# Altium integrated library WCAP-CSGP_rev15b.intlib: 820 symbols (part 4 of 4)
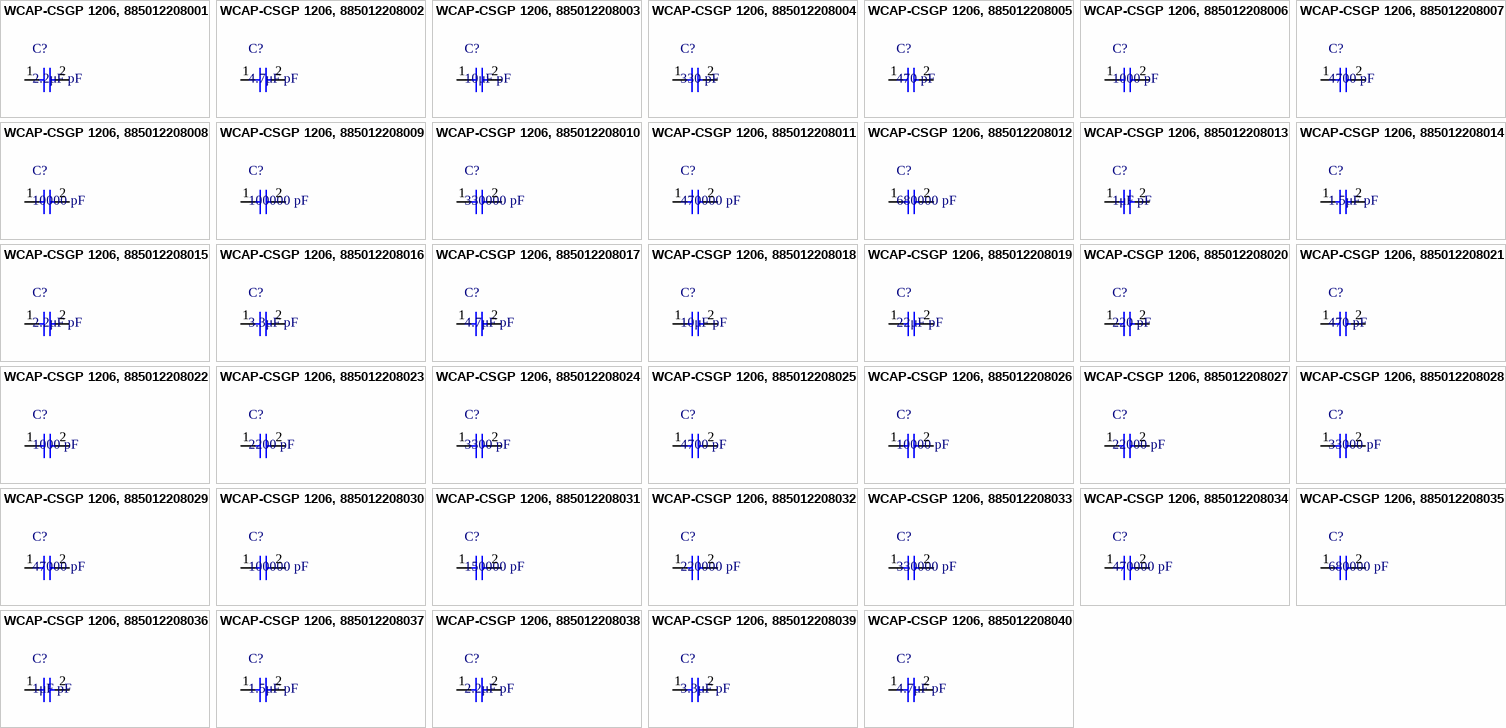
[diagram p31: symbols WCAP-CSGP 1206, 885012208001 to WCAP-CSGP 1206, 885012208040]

## WCAP-CSGP 1206, 885012208033
designator C?, comment 330000 pF
WCAP-CSGP MLCC, X7R, 1206, 330000 pF,16Vdc; Manufacturer: Wurth Elektronik; partNo: 885012208033; E-mail: libraries@we-online.com
footprint WCAP-CSGP 1206, H=0.95mm
pins: 1, 2

## WCAP-CSGP 1206, 885012208034
designator C?, comment 470000 pF
WCAP-CSGP MLCC, X7R, 1206, 470000 pF,16Vdc; Manufacturer: Wurth Elektronik; partNo: 885012208034; E-mail: libraries@we-online.com
footprint WCAP-CSGP 1206, H=1.15mm
pins: 1, 2

## WCAP-CSGP 1206, 885012208035
designator C?, comment 680000 pF
WCAP-CSGP MLCC, X7R, 1206, 680000 pF,16Vdc; Manufacturer: Wurth Elektronik; partNo: 885012208035; E-mail: libraries@we-online.com
footprint WCAP-CSGP 1206, H=1.15mm
pins: 1, 2

## WCAP-CSGP 1206, 885012208036
designator C?, comment 1μF pF
WCAP-CSGP MLCC, X7R, 1206, 1μF pF,16Vdc; Manufacturer: Wurth Elektronik; partNo: 885012208036; E-mail: libraries@we-online.com
footprint WCAP-CSGP 1206, H=1.15mm
pins: 1, 2

## WCAP-CSGP 1206, 885012208037
designator C?, comment 1.5μF pF
WCAP-CSGP MLCC, X7R, 1206, 1.5μF pF,16Vdc; Manufacturer: Wurth Elektronik; partNo: 885012208037; E-mail: libraries@we-online.com
footprint WCAP-CSGP 1206, H=1.15mm
pins: 1, 2

## WCAP-CSGP 1206, 885012208038
designator C?, comment 2.2μF pF
WCAP-CSGP MLCC, X7R, 1206, 2.2μF pF,16Vdc; Manufacturer: Wurth Elektronik; partNo: 885012208038; E-mail: libraries@we-online.com
footprint WCAP-CSGP 1206, H=1.15mm
pins: 1, 2

## WCAP-CSGP 1206, 885012208039
designator C?, comment 3.3μF pF
WCAP-CSGP MLCC, X7R, 1206, 3.3μF pF,16Vdc; Manufacturer: Wurth Elektronik; partNo: 885012208039; E-mail: libraries@we-online.com
footprint WCAP-CSGP 1206, H=1.6mm
pins: 1, 2

## WCAP-CSGP 1206, 885012208040
designator C?, comment 4.7μF pF
WCAP-CSGP MLCC, X7R, 1206, 4.7μF pF,16Vdc; Manufacturer: Wurth Elektronik; partNo: 885012208040; E-mail: libraries@we-online.com
footprint WCAP-CSGP 1206, H=1.6mm
pins: 1, 2

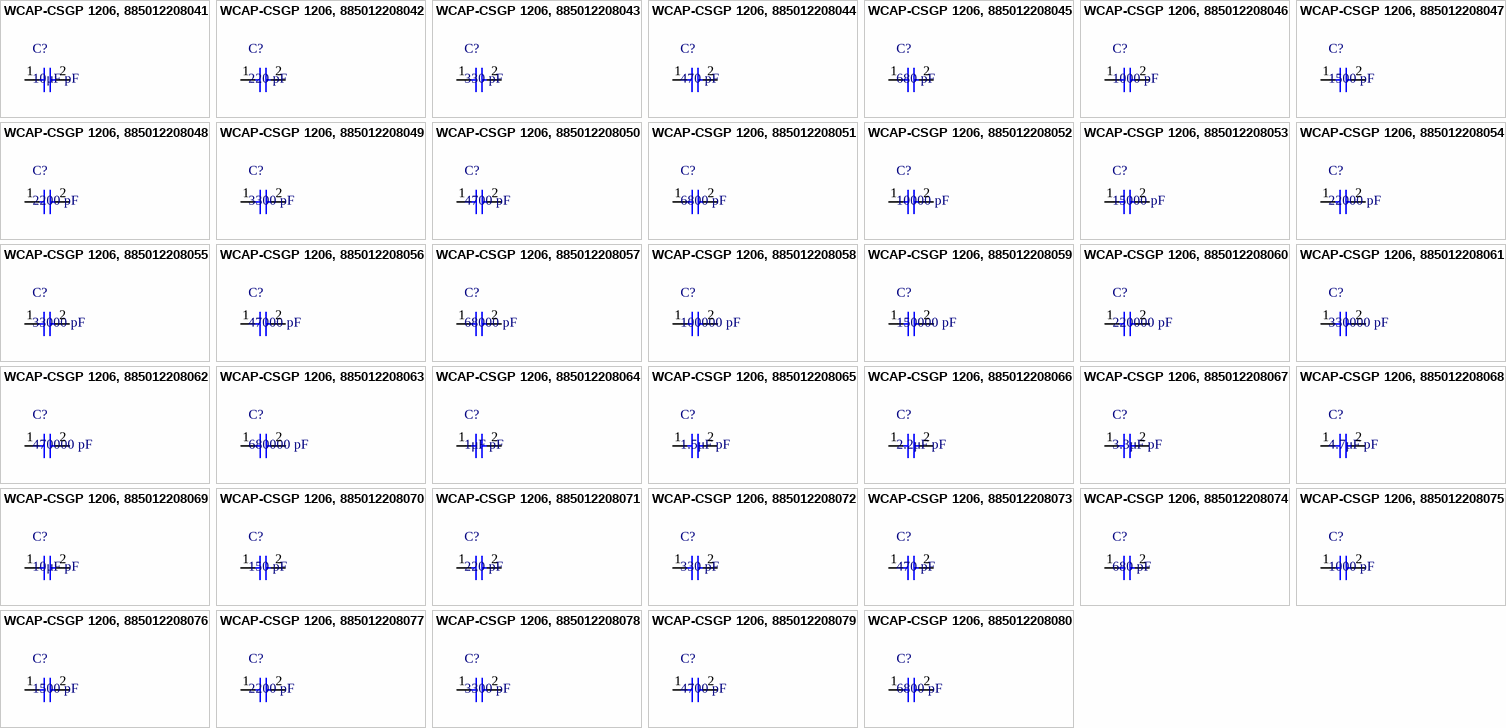
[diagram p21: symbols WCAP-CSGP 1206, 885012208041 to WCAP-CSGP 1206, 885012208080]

## WCAP-CSGP 1206, 885012208041
designator C?, comment 10μF pF
WCAP-CSGP MLCC, X7R, 1206, 10μF pF,16Vdc; Manufacturer: Wurth Elektronik; partNo: 885012208041; E-mail: libraries@we-online.com
footprint WCAP-CSGP 1206, H=1.6mm
pins: 1, 2

## WCAP-CSGP 1206, 885012208042
designator C?, comment 220 pF
WCAP-CSGP MLCC, X7R, 1206, 220 pF,25Vdc; Manufacturer: Wurth Elektronik; partNo: 885012208042; E-mail: libraries@we-online.com
footprint WCAP-CSGP 1206, H=0.8mm
pins: 1, 2

## WCAP-CSGP 1206, 885012208043
designator C?, comment 330 pF
WCAP-CSGP MLCC, X7R, 1206, 330 pF,25Vdc; Manufacturer: Wurth Elektronik; partNo: 885012208043; E-mail: libraries@we-online.com
footprint WCAP-CSGP 1206, H=0.8mm
pins: 1, 2

## WCAP-CSGP 1206, 885012208044
designator C?, comment 470 pF
WCAP-CSGP MLCC, X7R, 1206, 470 pF,25Vdc; Manufacturer: Wurth Elektronik; partNo: 885012208044; E-mail: libraries@we-online.com
footprint WCAP-CSGP 1206, H=0.8mm
pins: 1, 2

## WCAP-CSGP 1206, 885012208045
designator C?, comment 680 pF
WCAP-CSGP MLCC, X7R, 1206, 680 pF,25Vdc; Manufacturer: Wurth Elektronik; partNo: 885012208045; E-mail: libraries@we-online.com
footprint WCAP-CSGP 1206, H=0.8mm
pins: 1, 2

## WCAP-CSGP 1206, 885012208046
designator C?, comment 1000 pF
WCAP-CSGP MLCC, X7R, 1206, 1000 pF,25Vdc; Manufacturer: Wurth Elektronik; partNo: 885012208046; E-mail: libraries@we-online.com
footprint WCAP-CSGP 1206, H=0.8mm
pins: 1, 2

## WCAP-CSGP 1206, 885012208047
designator C?, comment 1500 pF
WCAP-CSGP MLCC, X7R, 1206, 1500 pF,25Vdc; Manufacturer: Wurth Elektronik; partNo: 885012208047; E-mail: libraries@we-online.com
footprint WCAP-CSGP 1206, H=0.8mm
pins: 1, 2

## WCAP-CSGP 1206, 885012208048
designator C?, comment 2200 pF
WCAP-CSGP MLCC, X7R, 1206, 2200 pF,25Vdc; Manufacturer: Wurth Elektronik; partNo: 885012208048; E-mail: libraries@we-online.com
footprint WCAP-CSGP 1206, H=0.8mm
pins: 1, 2

## WCAP-CSGP 1206, 885012208049
designator C?, comment 3300 pF
WCAP-CSGP MLCC, X7R, 1206, 3300 pF,25Vdc; Manufacturer: Wurth Elektronik; partNo: 885012208049; E-mail: libraries@we-online.com
footprint WCAP-CSGP 1206, H=0.8mm
pins: 1, 2

## WCAP-CSGP 1206, 885012208050
designator C?, comment 4700 pF
WCAP-CSGP MLCC, X7R, 1206, 4700 pF,25Vdc; Manufacturer: Wurth Elektronik; partNo: 885012208050; E-mail: libraries@we-online.com
footprint WCAP-CSGP 1206, H=0.8mm
pins: 1, 2

## WCAP-CSGP 1206, 885012208051
designator C?, comment 6800 pF
WCAP-CSGP MLCC, X7R, 1206, 6800 pF,25Vdc; Manufacturer: Wurth Elektronik; partNo: 885012208051; E-mail: libraries@we-online.com
footprint WCAP-CSGP 1206, H=0.8mm
pins: 1, 2

## WCAP-CSGP 1206, 885012208052
designator C?, comment 10000 pF
WCAP-CSGP MLCC, X7R, 1206, 10000 pF,25Vdc; Manufacturer: Wurth Elektronik; partNo: 885012208052; E-mail: libraries@we-online.com
footprint WCAP-CSGP 1206, H=0.8mm
pins: 1, 2

## WCAP-CSGP 1206, 885012208053
designator C?, comment 15000 pF
WCAP-CSGP MLCC, X7R, 1206, 15000 pF,25Vdc; Manufacturer: Wurth Elektronik; partNo: 885012208053; E-mail: libraries@we-online.com
footprint WCAP-CSGP 1206, H=0.8mm
pins: 1, 2

## WCAP-CSGP 1206, 885012208054
designator C?, comment 22000 pF
WCAP-CSGP MLCC, X7R, 1206, 22000 pF,25Vdc; Manufacturer: Wurth Elektronik; partNo: 885012208054; E-mail: libraries@we-online.com
footprint WCAP-CSGP 1206, H=0.8mm
pins: 1, 2

## WCAP-CSGP 1206, 885012208055
designator C?, comment 33000 pF
WCAP-CSGP MLCC, X7R, 1206, 33000 pF,25Vdc; Manufacturer: Wurth Elektronik; partNo: 885012208055; E-mail: libraries@we-online.com
footprint WCAP-CSGP 1206, H=0.8mm
pins: 1, 2

## WCAP-CSGP 1206, 885012208056
designator C?, comment 47000 pF
WCAP-CSGP MLCC, X7R, 1206, 47000 pF,25Vdc; Manufacturer: Wurth Elektronik; partNo: 885012208056; E-mail: libraries@we-online.com
footprint WCAP-CSGP 1206, H=0.8mm
pins: 1, 2

## WCAP-CSGP 1206, 885012208057
designator C?, comment 68000 pF
WCAP-CSGP MLCC, X7R, 1206, 68000 pF,25Vdc; Manufacturer: Wurth Elektronik; partNo: 885012208057; E-mail: libraries@we-online.com
footprint WCAP-CSGP 1206, H=0.8mm
pins: 1, 2

## WCAP-CSGP 1206, 885012208058
designator C?, comment 100000 pF
WCAP-CSGP MLCC, X7R, 1206, 100000 pF,25Vdc; Manufacturer: Wurth Elektronik; partNo: 885012208058; E-mail: libraries@we-online.com
footprint WCAP-CSGP 1206, H=0.8mm
pins: 1, 2

## WCAP-CSGP 1206, 885012208059
designator C?, comment 150000 pF
WCAP-CSGP MLCC, X7R, 1206, 150000 pF,25Vdc; Manufacturer: Wurth Elektronik; partNo: 885012208059; E-mail: libraries@we-online.com
footprint WCAP-CSGP 1206, H=0.95mm
pins: 1, 2

## WCAP-CSGP 1206, 885012208060
designator C?, comment 220000 pF
WCAP-CSGP MLCC, X7R, 1206, 220000 pF,25Vdc; Manufacturer: Wurth Elektronik; partNo: 885012208060; E-mail: libraries@we-online.com
footprint WCAP-CSGP 1206, H=0.95mm
pins: 1, 2

## WCAP-CSGP 1206, 885012208061
designator C?, comment 330000 pF
WCAP-CSGP MLCC, X7R, 1206, 330000 pF,25Vdc; Manufacturer: Wurth Elektronik; partNo: 885012208061; E-mail: libraries@we-online.com
footprint WCAP-CSGP 1206, H=0.95mm
pins: 1, 2

## WCAP-CSGP 1206, 885012208062
designator C?, comment 470000 pF
WCAP-CSGP MLCC, X7R, 1206, 470000 pF,25Vdc; Manufacturer: Wurth Elektronik; partNo: 885012208062; E-mail: libraries@we-online.com
footprint WCAP-CSGP 1206, H=1.15mm
pins: 1, 2

## WCAP-CSGP 1206, 885012208063
designator C?, comment 680000 pF
WCAP-CSGP MLCC, X7R, 1206, 680000 pF,25Vdc; Manufacturer: Wurth Elektronik; partNo: 885012208063; E-mail: libraries@we-online.com
footprint WCAP-CSGP 1206, H=1.15mm
pins: 1, 2

## WCAP-CSGP 1206, 885012208064
designator C?, comment 1μF pF
WCAP-CSGP MLCC, X7R, 1206, 1μF pF,25Vdc; Manufacturer: Wurth Elektronik; partNo: 885012208064; E-mail: libraries@we-online.com
footprint WCAP-CSGP 1206, H=1.15mm
pins: 1, 2

## WCAP-CSGP 1206, 885012208065
designator C?, comment 1.5μF pF
WCAP-CSGP MLCC, X7R, 1206, 1.5μF pF,25Vdc; Manufacturer: Wurth Elektronik; partNo: 885012208065; E-mail: libraries@we-online.com
footprint WCAP-CSGP 1206, H=1.6mm
pins: 1, 2

## WCAP-CSGP 1206, 885012208066
designator C?, comment 2.2μF pF
WCAP-CSGP MLCC, X7R, 1206, 2.2μF pF,25Vdc; Manufacturer: Wurth Elektronik; partNo: 885012208066; E-mail: libraries@we-online.com
footprint WCAP-CSGP 1206, H=1.6mm
pins: 1, 2

## WCAP-CSGP 1206, 885012208067
designator C?, comment 3.3μF pF
WCAP-CSGP MLCC, X7R, 1206, 3.3μF pF,25Vdc; Manufacturer: Wurth Elektronik; partNo: 885012208067; E-mail: libraries@we-online.com
footprint WCAP-CSGP 1206, H=1.6mm
pins: 1, 2

## WCAP-CSGP 1206, 885012208068
designator C?, comment 4.7μF pF
WCAP-CSGP MLCC, X7R, 1206, 4.7μF pF,25Vdc; Manufacturer: Wurth Elektronik; partNo: 885012208068; E-mail: libraries@we-online.com
footprint WCAP-CSGP 1206, H=1.6mm
pins: 1, 2

## WCAP-CSGP 1206, 885012208069
designator C?, comment 10μF pF
WCAP-CSGP MLCC, X7R, 1206, 10μF pF,25Vdc; Manufacturer: Wurth Elektronik; partNo: 885012208069; E-mail: libraries@we-online.com
footprint WCAP-CSGP 1206, H=1.6mm
pins: 1, 2

## WCAP-CSGP 1206, 885012208070
designator C?, comment 150 pF
WCAP-CSGP MLCC, X7R, 1206, 150 pF,50Vdc; Manufacturer: Wurth Elektronik; partNo: 885012208070; E-mail: libraries@we-online.com
footprint WCAP-CSGP 1206, H=0.8mm
pins: 1, 2

## WCAP-CSGP 1206, 885012208071
designator C?, comment 220 pF
WCAP-CSGP MLCC, X7R, 1206, 220 pF,50Vdc; Manufacturer: Wurth Elektronik; partNo: 885012208071; E-mail: libraries@we-online.com
footprint WCAP-CSGP 1206, H=0.8mm
pins: 1, 2

## WCAP-CSGP 1206, 885012208072
designator C?, comment 330 pF
WCAP-CSGP MLCC, X7R, 1206, 330 pF,50Vdc; Manufacturer: Wurth Elektronik; partNo: 885012208072; E-mail: libraries@we-online.com
footprint WCAP-CSGP 1206, H=0.8mm
pins: 1, 2

## WCAP-CSGP 1206, 885012208073
designator C?, comment 470 pF
WCAP-CSGP MLCC, X7R, 1206, 470 pF,50Vdc; Manufacturer: Wurth Elektronik; partNo: 885012208073; E-mail: libraries@we-online.com
footprint WCAP-CSGP 1206, H=0.8mm
pins: 1, 2

## WCAP-CSGP 1206, 885012208074
designator C?, comment 680 pF
WCAP-CSGP MLCC, X7R, 1206, 680 pF,50Vdc; Manufacturer: Wurth Elektronik; partNo: 885012208074; E-mail: libraries@we-online.com
footprint WCAP-CSGP 1206, H=0.8mm
pins: 1, 2

## WCAP-CSGP 1206, 885012208075
designator C?, comment 1000 pF
WCAP-CSGP MLCC, X7R, 1206, 1000 pF,50Vdc; Manufacturer: Wurth Elektronik; partNo: 885012208075; E-mail: libraries@we-online.com
footprint WCAP-CSGP 1206, H=0.8mm
pins: 1, 2

## WCAP-CSGP 1206, 885012208076
designator C?, comment 1500 pF
WCAP-CSGP MLCC, X7R, 1206, 1500 pF,50Vdc; Manufacturer: Wurth Elektronik; partNo: 885012208076; E-mail: libraries@we-online.com
footprint WCAP-CSGP 1206, H=0.8mm
pins: 1, 2

## WCAP-CSGP 1206, 885012208077
designator C?, comment 2200 pF
WCAP-CSGP MLCC, X7R, 1206, 2200 pF,50Vdc; Manufacturer: Wurth Elektronik; partNo: 885012208077; E-mail: libraries@we-online.com
footprint WCAP-CSGP 1206, H=0.8mm
pins: 1, 2

## WCAP-CSGP 1206, 885012208078
designator C?, comment 3300 pF
WCAP-CSGP MLCC, X7R, 1206, 3300 pF,50Vdc; Manufacturer: Wurth Elektronik; partNo: 885012208078; E-mail: libraries@we-online.com
footprint WCAP-CSGP 1206, H=0.8mm
pins: 1, 2

## WCAP-CSGP 1206, 885012208079
designator C?, comment 4700 pF
WCAP-CSGP MLCC, X7R, 1206, 4700 pF,50Vdc; Manufacturer: Wurth Elektronik; partNo: 885012208079; E-mail: libraries@we-online.com
footprint WCAP-CSGP 1206, H=0.8mm
pins: 1, 2

## WCAP-CSGP 1206, 885012208080
designator C?, comment 6800 pF
WCAP-CSGP MLCC, X7R, 1206, 6800 pF,50Vdc; Manufacturer: Wurth Elektronik; partNo: 885012208080; E-mail: libraries@we-online.com
footprint WCAP-CSGP 1206, H=0.8mm
pins: 1, 2

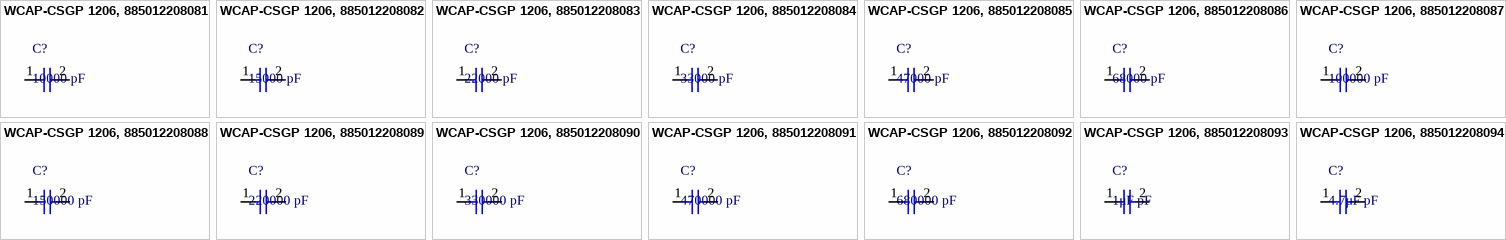
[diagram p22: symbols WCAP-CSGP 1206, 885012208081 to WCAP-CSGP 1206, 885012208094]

## WCAP-CSGP 1206, 885012208081
designator C?, comment 10000 pF
WCAP-CSGP MLCC, X7R, 1206, 10000 pF,50Vdc; Manufacturer: Wurth Elektronik; partNo: 885012208081; E-mail: libraries@we-online.com
footprint WCAP-CSGP 1206, H=0.8mm
pins: 1, 2

## WCAP-CSGP 1206, 885012208082
designator C?, comment 15000 pF
WCAP-CSGP MLCC, X7R, 1206, 15000 pF,50Vdc; Manufacturer: Wurth Elektronik; partNo: 885012208082; E-mail: libraries@we-online.com
footprint WCAP-CSGP 1206, H=0.8mm
pins: 1, 2

## WCAP-CSGP 1206, 885012208083
designator C?, comment 22000 pF
WCAP-CSGP MLCC, X7R, 1206, 22000 pF,50Vdc; Manufacturer: Wurth Elektronik; partNo: 885012208083; E-mail: libraries@we-online.com
footprint WCAP-CSGP 1206, H=0.8mm
pins: 1, 2

## WCAP-CSGP 1206, 885012208084
designator C?, comment 33000 pF
WCAP-CSGP MLCC, X7R, 1206, 33000 pF,50Vdc; Manufacturer: Wurth Elektronik; partNo: 885012208084; E-mail: libraries@we-online.com
footprint WCAP-CSGP 1206, H=0.8mm
pins: 1, 2

## WCAP-CSGP 1206, 885012208085
designator C?, comment 47000 pF
WCAP-CSGP MLCC, X7R, 1206, 47000 pF,50Vdc; Manufacturer: Wurth Elektronik; partNo: 885012208085; E-mail: libraries@we-online.com
footprint WCAP-CSGP 1206, H=0.8mm
pins: 1, 2

## WCAP-CSGP 1206, 885012208086
designator C?, comment 68000 pF
WCAP-CSGP MLCC, X7R, 1206, 68000 pF,50Vdc; Manufacturer: Wurth Elektronik; partNo: 885012208086; E-mail: libraries@we-online.com
footprint WCAP-CSGP 1206, H=0.8mm
pins: 1, 2

## WCAP-CSGP 1206, 885012208087
designator C?, comment 100000 pF
WCAP-CSGP MLCC, X7R, 1206, 100000 pF,50Vdc; Manufacturer: Wurth Elektronik; partNo: 885012208087; E-mail: libraries@we-online.com
footprint WCAP-CSGP 1206, H=0.8mm
pins: 1, 2

## WCAP-CSGP 1206, 885012208088
designator C?, comment 150000 pF
WCAP-CSGP MLCC, X7R, 1206, 150000 pF,50Vdc; Manufacturer: Wurth Elektronik; partNo: 885012208088; E-mail: libraries@we-online.com
footprint WCAP-CSGP 1206, H=0.95mm
pins: 1, 2

## WCAP-CSGP 1206, 885012208089
designator C?, comment 220000 pF
WCAP-CSGP MLCC, X7R, 1206, 220000 pF,50Vdc; Manufacturer: Wurth Elektronik; partNo: 885012208089; E-mail: libraries@we-online.com
footprint WCAP-CSGP 1206, H=0.95mm
pins: 1, 2

## WCAP-CSGP 1206, 885012208090
designator C?, comment 330000 pF
WCAP-CSGP MLCC, X7R, 1206, 330000 pF,50Vdc; Manufacturer: Wurth Elektronik; partNo: 885012208090; E-mail: libraries@we-online.com
footprint WCAP-CSGP 1206, H=1.25mm
pins: 1, 2

## WCAP-CSGP 1206, 885012208091
designator C?, comment 470000 pF
WCAP-CSGP MLCC, X7R, 1206, 470000 pF,50Vdc; Manufacturer: Wurth Elektronik; partNo: 885012208091; E-mail: libraries@we-online.com
footprint WCAP-CSGP 1206, H=1.6mm
pins: 1, 2

## WCAP-CSGP 1206, 885012208092
designator C?, comment 680000 pF
WCAP-CSGP MLCC, X7R, 1206, 680000 pF,50Vdc; Manufacturer: Wurth Elektronik; partNo: 885012208092; E-mail: libraries@we-online.com
footprint WCAP-CSGP 1206, H=1.6mm
pins: 1, 2

## WCAP-CSGP 1206, 885012208093
designator C?, comment 1μF pF
WCAP-CSGP MLCC, X7R, 1206, 1μF pF,50Vdc; Manufacturer: Wurth Elektronik; partNo: 885012208093; E-mail: libraries@we-online.com
footprint WCAP-CSGP 1206, H=1.6mm
pins: 1, 2

## WCAP-CSGP 1206, 885012208094
designator C?, comment 4.7μF pF
WCAP-CSGP MLCC, X7R, 1206, 4.7μF pF,50Vdc; Manufacturer: Wurth Elektronik; partNo: 885012208094; E-mail: libraries@we-online.com
footprint WCAP-CSGP 1206, H=1.6mm
pins: 1, 2


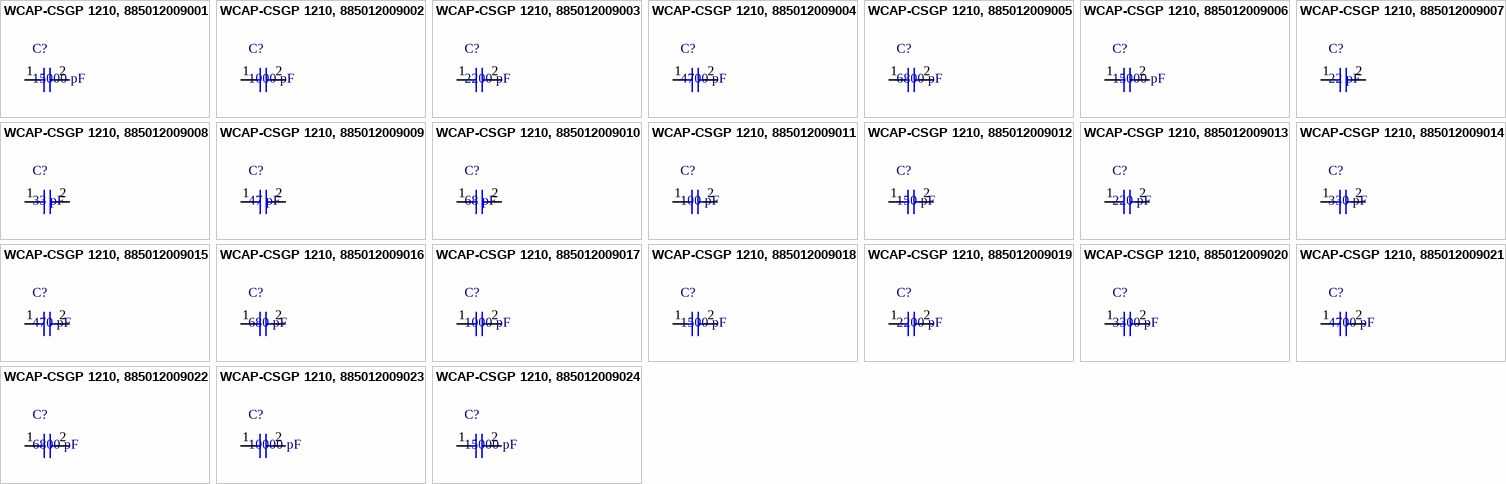
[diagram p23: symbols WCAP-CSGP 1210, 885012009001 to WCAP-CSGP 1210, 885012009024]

## WCAP-CSGP 1210, 885012009001
designator C?, comment 15000 pF
WCAP-CSGP MLCC, NP0, 1210, 15000 pF,16Vdc; Manufacturer: Wurth Elektronik; partNo: 885012009001; E-mail: libraries@we-online.com
footprint WCAP-CSGP 1210, H=1.25mm (MLCC 1210, H=0.95mm)
pins: 1, 2

## WCAP-CSGP 1210, 885012009002
designator C?, comment 1000 pF
WCAP-CSGP MLCC, NP0, 1210, 1000 pF,25Vdc; Manufacturer: Wurth Elektronik; partNo: 885012009002; E-mail: libraries@we-online.com
footprint WCAP-CSGP 1210, H=0.95mm
pins: 1, 2

## WCAP-CSGP 1210, 885012009003
designator C?, comment 2200 pF
WCAP-CSGP MLCC, NP0, 1210, 2200 pF,25Vdc; Manufacturer: Wurth Elektronik; partNo: 885012009003; E-mail: libraries@we-online.com
footprint WCAP-CSGP 1210, H=0.95mm
pins: 1, 2

## WCAP-CSGP 1210, 885012009004
designator C?, comment 4700 pF
WCAP-CSGP MLCC, NP0, 1210, 4700 pF,25Vdc; Manufacturer: Wurth Elektronik; partNo: 885012009004; E-mail: libraries@we-online.com
footprint WCAP-CSGP 1210, H=0.95mm
pins: 1, 2

## WCAP-CSGP 1210, 885012009005
designator C?, comment 6800 pF
WCAP-CSGP MLCC, NP0, 1210, 6800 pF,25Vdc; Manufacturer: Wurth Elektronik; partNo: 885012009005; E-mail: libraries@we-online.com
footprint WCAP-CSGP 1210, H=0.95mm
pins: 1, 2

## WCAP-CSGP 1210, 885012009006
designator C?, comment 15000 pF
WCAP-CSGP MLCC, NP0, 1210, 15000 pF,25Vdc; Manufacturer: Wurth Elektronik; partNo: 885012009006; E-mail: libraries@we-online.com
footprint WCAP-CSGP 1210, H=1.25mm
pins: 1, 2

## WCAP-CSGP 1210, 885012009007
designator C?, comment 22 pF
WCAP-CSGP MLCC, NP0, 1210, 22 pF,50Vdc; Manufacturer: Wurth Elektronik; partNo: 885012009007; E-mail: libraries@we-online.com
footprint WCAP-CSGP 1210, H=0.95mm
pins: 1, 2

## WCAP-CSGP 1210, 885012009008
designator C?, comment 33 pF
WCAP-CSGP MLCC, NP0, 1210, 33 pF,50Vdc; Manufacturer: Wurth Elektronik; partNo: 885012009008; E-mail: libraries@we-online.com
footprint WCAP-CSGP 1210, H=0.95mm
pins: 1, 2

## WCAP-CSGP 1210, 885012009009
designator C?, comment 47 pF
WCAP-CSGP MLCC, NP0, 1210, 47 pF,50Vdc; Manufacturer: Wurth Elektronik; partNo: 885012009009; E-mail: libraries@we-online.com
footprint WCAP-CSGP 1210, H=0.95mm
pins: 1, 2

## WCAP-CSGP 1210, 885012009010
designator C?, comment 68 pF
WCAP-CSGP MLCC, NP0, 1210, 68 pF,50Vdc; Manufacturer: Wurth Elektronik; partNo: 885012009010; E-mail: libraries@we-online.com
footprint WCAP-CSGP 1210, H=0.95mm
pins: 1, 2

## WCAP-CSGP 1210, 885012009011
designator C?, comment 100 pF
WCAP-CSGP MLCC, NP0, 1210, 100 pF,50Vdc; Manufacturer: Wurth Elektronik; partNo: 885012009011; E-mail: libraries@we-online.com
footprint WCAP-CSGP 1210, H=0.95mm
pins: 1, 2

## WCAP-CSGP 1210, 885012009012
designator C?, comment 150 pF
WCAP-CSGP MLCC, NP0, 1210, 150 pF,50Vdc; Manufacturer: Wurth Elektronik; partNo: 885012009012; E-mail: libraries@we-online.com
footprint WCAP-CSGP 1210, H=0.95mm
pins: 1, 2

## WCAP-CSGP 1210, 885012009013
designator C?, comment 220 pF
WCAP-CSGP MLCC, NP0, 1210, 220 pF,50Vdc; Manufacturer: Wurth Elektronik; partNo: 885012009013; E-mail: libraries@we-online.com
footprint WCAP-CSGP 1210, H=0.95mm
pins: 1, 2

## WCAP-CSGP 1210, 885012009014
designator C?, comment 330 pF
WCAP-CSGP MLCC, NP0, 1210, 330 pF,50Vdc; Manufacturer: Wurth Elektronik; partNo: 885012009014; E-mail: libraries@we-online.com
footprint WCAP-CSGP 1210, H=0.95mm
pins: 1, 2

## WCAP-CSGP 1210, 885012009015
designator C?, comment 470 pF
WCAP-CSGP MLCC, NP0, 1210, 470 pF,50Vdc; Manufacturer: Wurth Elektronik; partNo: 885012009015; E-mail: libraries@we-online.com
footprint WCAP-CSGP 1210, H=0.95mm
pins: 1, 2

## WCAP-CSGP 1210, 885012009016
designator C?, comment 680 pF
WCAP-CSGP MLCC, NP0, 1210, 680 pF,50Vdc; Manufacturer: Wurth Elektronik; partNo: 885012009016; E-mail: libraries@we-online.com
footprint WCAP-CSGP 1210, H=0.95mm
pins: 1, 2

## WCAP-CSGP 1210, 885012009017
designator C?, comment 1000 pF
WCAP-CSGP MLCC, NP0, 1210, 1000 pF,50Vdc; Manufacturer: Wurth Elektronik; partNo: 885012009017; E-mail: libraries@we-online.com
footprint WCAP-CSGP 1210, H=0.95mm
pins: 1, 2

## WCAP-CSGP 1210, 885012009018
designator C?, comment 1500 pF
WCAP-CSGP MLCC, NP0, 1210, 1500 pF,50Vdc; Manufacturer: Wurth Elektronik; partNo: 885012009018; E-mail: libraries@we-online.com
footprint WCAP-CSGP 1210, H=0.95mm
pins: 1, 2

## WCAP-CSGP 1210, 885012009019
designator C?, comment 2200 pF
WCAP-CSGP MLCC, NP0, 1210, 2200 pF,50Vdc; Manufacturer: Wurth Elektronik; partNo: 885012009019; E-mail: libraries@we-online.com
footprint WCAP-CSGP 1210, H=0.95mm
pins: 1, 2

## WCAP-CSGP 1210, 885012009020
designator C?, comment 3300 pF
WCAP-CSGP MLCC, NP0, 1210, 3300 pF,50Vdc; Manufacturer: Wurth Elektronik; partNo: 885012009020; E-mail: libraries@we-online.com
footprint WCAP-CSGP 1210, H=0.95mm
pins: 1, 2

## WCAP-CSGP 1210, 885012009021
designator C?, comment 4700 pF
WCAP-CSGP MLCC, NP0, 1210, 4700 pF,50Vdc; Manufacturer: Wurth Elektronik; partNo: 885012009021; E-mail: libraries@we-online.com
footprint WCAP-CSGP 1210, H=0.95mm
pins: 1, 2

## WCAP-CSGP 1210, 885012009022
designator C?, comment 6800 pF
WCAP-CSGP MLCC, NP0, 1210, 6800 pF,50Vdc; Manufacturer: Wurth Elektronik; partNo: 885012009022; E-mail: libraries@we-online.com
footprint WCAP-CSGP 1210, H=0.95mm
pins: 1, 2

## WCAP-CSGP 1210, 885012009023
designator C?, comment 10000 pF
WCAP-CSGP MLCC, NP0, 1210, 10000 pF,50Vdc; Manufacturer: Wurth Elektronik; partNo: 885012009023; E-mail: libraries@we-online.com
footprint WCAP-CSGP 1210, H=0.95mm
pins: 1, 2

## WCAP-CSGP 1210, 885012009024
designator C?, comment 15000 pF
WCAP-CSGP MLCC, NP0, 1210, 15000 pF,50Vdc; Manufacturer: Wurth Elektronik; partNo: 885012009024; E-mail: libraries@we-online.com
footprint WCAP-CSGP 1210, H=1.25mm
pins: 1, 2


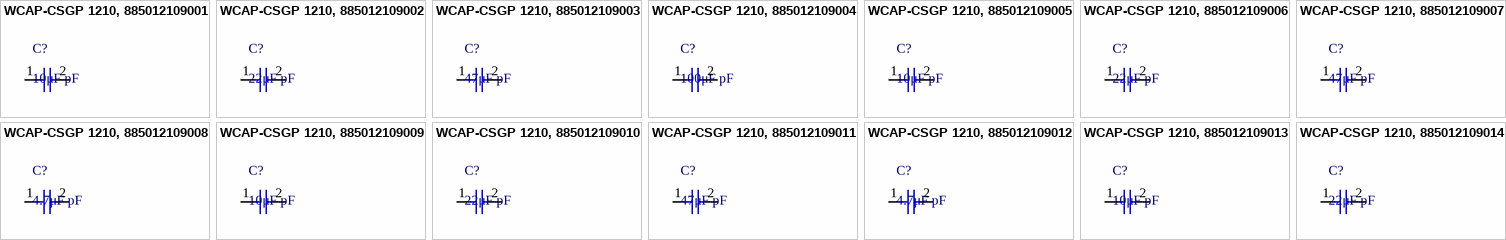
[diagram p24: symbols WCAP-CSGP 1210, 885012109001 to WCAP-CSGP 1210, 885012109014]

## WCAP-CSGP 1210, 885012109001
designator C?, comment 10μF pF
WCAP-CSGP MLCC, X5R, 1210, 10μF pF,6.3Vdc; Manufacturer: Wurth Elektronik; partNo: 885012109001; E-mail: libraries@we-online.com
footprint WCAP-CSGP 1210, H=2mm
pins: 1, 2

## WCAP-CSGP 1210, 885012109002
designator C?, comment 22μF pF
WCAP-CSGP MLCC, X5R, 1210, 22μF pF,6.3Vdc; Manufacturer: Wurth Elektronik; partNo: 885012109002; E-mail: libraries@we-online.com
footprint WCAP-CSGP 1210, H=2.5mm
pins: 1, 2

## WCAP-CSGP 1210, 885012109003
designator C?, comment 47μF pF
WCAP-CSGP MLCC, X5R, 1210, 47μF pF,6.3Vdc; Manufacturer: Wurth Elektronik; partNo: 885012109003; E-mail: libraries@we-online.com
footprint WCAP-CSGP 1210, H=2.5mm
pins: 1, 2

## WCAP-CSGP 1210, 885012109004
designator C?, comment 100μF pF
WCAP-CSGP MLCC, X5R, 1210, 100μF pF,6.3Vdc; Manufacturer: Wurth Elektronik; partNo: 885012109004; E-mail: libraries@we-online.com
footprint WCAP-CSGP 1210, H=2.5mm
pins: 1, 2

## WCAP-CSGP 1210, 885012109005
designator C?, comment 10μF pF
WCAP-CSGP MLCC, X5R, 1210, 10μF pF,10Vdc; Manufacturer: Wurth Elektronik; partNo: 885012109005; E-mail: libraries@we-online.com
footprint WCAP-CSGP 1210, H=2mm
pins: 1, 2

## WCAP-CSGP 1210, 885012109006
designator C?, comment 22μF pF
WCAP-CSGP MLCC, X5R, 1210, 22μF pF,10Vdc; Manufacturer: Wurth Elektronik; partNo: 885012109006; E-mail: libraries@we-online.com
footprint WCAP-CSGP 1210, H=2.5mm
pins: 1, 2

## WCAP-CSGP 1210, 885012109007
designator C?, comment 47μF pF
WCAP-CSGP MLCC, X5R, 1210, 47μF pF,10Vdc; Manufacturer: Wurth Elektronik; partNo: 885012109007; E-mail: libraries@we-online.com
footprint WCAP-CSGP 1210, H=2.5mm
pins: 1, 2

## WCAP-CSGP 1210, 885012109008
designator C?, comment 4.7μF pF
WCAP-CSGP MLCC, X5R, 1210, 4.7μF pF,16Vdc; Manufacturer: Wurth Elektronik; partNo: 885012109008; E-mail: libraries@we-online.com
footprint WCAP-CSGP 1210, H=2mm
pins: 1, 2

## WCAP-CSGP 1210, 885012109009
designator C?, comment 10μF pF
WCAP-CSGP MLCC, X5R, 1210, 10μF pF,16Vdc; Manufacturer: Wurth Elektronik; partNo: 885012109009; E-mail: libraries@we-online.com
footprint WCAP-CSGP 1210, H=2mm
pins: 1, 2

## WCAP-CSGP 1210, 885012109010
designator C?, comment 22μF pF
WCAP-CSGP MLCC, X5R, 1210, 22μF pF,16Vdc; Manufacturer: Wurth Elektronik; partNo: 885012109010; E-mail: libraries@we-online.com
footprint WCAP-CSGP 1210, H=2.5mm
pins: 1, 2

## WCAP-CSGP 1210, 885012109011
designator C?, comment 47μF pF
WCAP-CSGP MLCC, X5R, 1210, 47μF pF,16Vdc; Manufacturer: Wurth Elektronik; partNo: 885012109011; E-mail: libraries@we-online.com
footprint WCAP-CSGP 1210, H=2.5mm
pins: 1, 2

## WCAP-CSGP 1210, 885012109012
designator C?, comment 4.7μF pF
WCAP-CSGP MLCC, X5R, 1210, 4.7μF pF,25Vdc; Manufacturer: Wurth Elektronik; partNo: 885012109012; E-mail: libraries@we-online.com
footprint WCAP-CSGP 1210, H=2mm
pins: 1, 2

## WCAP-CSGP 1210, 885012109013
designator C?, comment 10μF pF
WCAP-CSGP MLCC, X5R, 1210, 10μF pF,25Vdc; Manufacturer: Wurth Elektronik; partNo: 885012109013; E-mail: libraries@we-online.com
footprint WCAP-CSGP 1210, H=2mm
pins: 1, 2

## WCAP-CSGP 1210, 885012109014
designator C?, comment 22μF pF
WCAP-CSGP MLCC, X5R, 1210, 22μF pF,25Vdc; Manufacturer: Wurth Elektronik; partNo: 885012109014; E-mail: libraries@we-online.com
footprint WCAP-CSGP 1210, H=2.5mm
pins: 1, 2


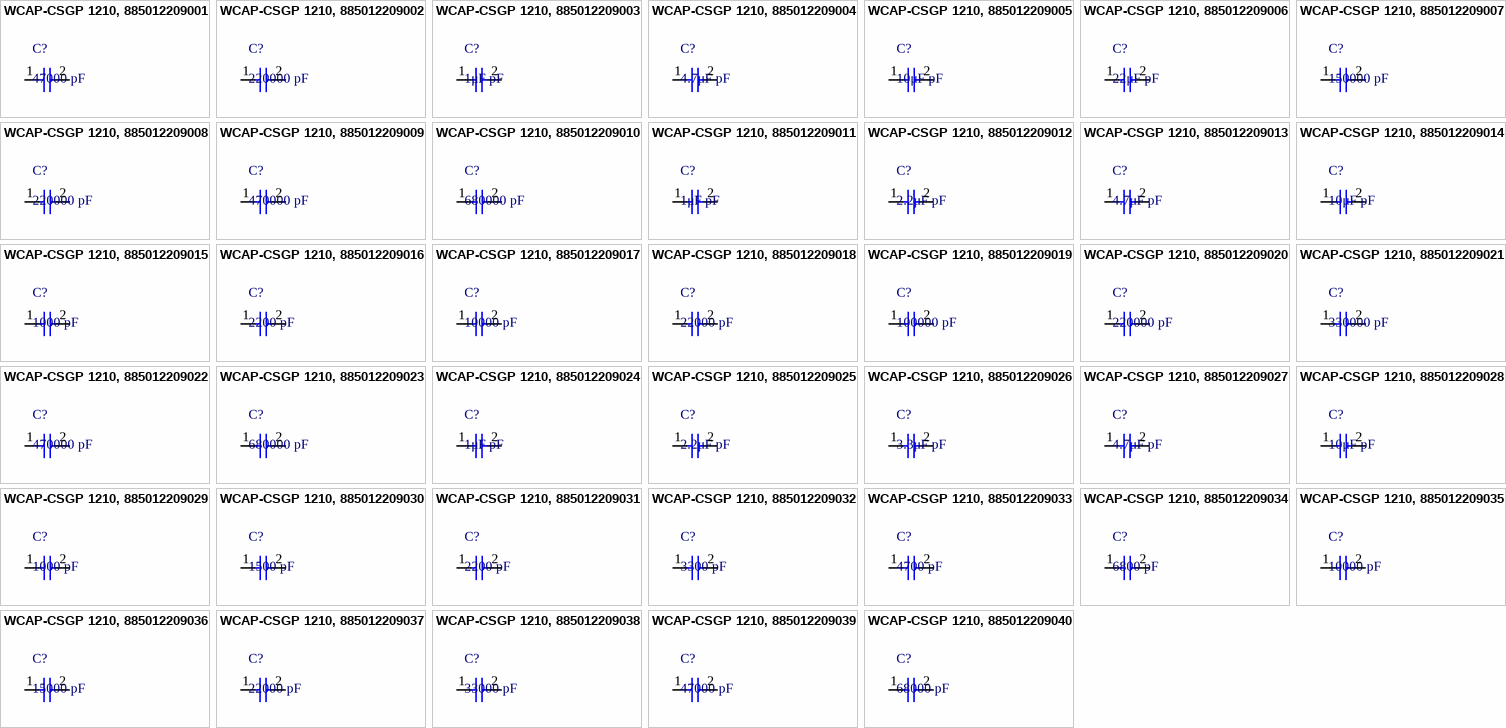
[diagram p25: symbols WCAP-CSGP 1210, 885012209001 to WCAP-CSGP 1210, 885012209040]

## WCAP-CSGP 1210, 885012209001
designator C?, comment 47000 pF
WCAP-CSGP MLCC, X7R, 1210, 47000 pF,10Vdc; Manufacturer: Wurth Elektronik; partNo: 885012209001; E-mail: libraries@we-online.com
footprint WCAP-CSGP 1210, H=0.95mm
pins: 1, 2

## WCAP-CSGP 1210, 885012209002
designator C?, comment 220000 pF
WCAP-CSGP MLCC, X7R, 1210, 220000 pF,10Vdc; Manufacturer: Wurth Elektronik; partNo: 885012209002; E-mail: libraries@we-online.com
footprint WCAP-CSGP 1210, H=0.95mm
pins: 1, 2

## WCAP-CSGP 1210, 885012209003
designator C?, comment 1μF pF
WCAP-CSGP MLCC, X7R, 1210, 1μF pF,10Vdc; Manufacturer: Wurth Elektronik; partNo: 885012209003; E-mail: libraries@we-online.com
footprint WCAP-CSGP 1210, H=1.25mm
pins: 1, 2

## WCAP-CSGP 1210, 885012209004
designator C?, comment 4.7μF pF
WCAP-CSGP MLCC, X7R, 1210, 4.7μF pF,10Vdc; Manufacturer: Wurth Elektronik; partNo: 885012209004; E-mail: libraries@we-online.com
footprint WCAP-CSGP 1210, H=2mm
pins: 1, 2

## WCAP-CSGP 1210, 885012209005
designator C?, comment 10μF pF
WCAP-CSGP MLCC, X7R, 1210, 10μF pF,10Vdc; Manufacturer: Wurth Elektronik; partNo: 885012209005; E-mail: libraries@we-online.com
footprint WCAP-CSGP 1210, H=2mm
pins: 1, 2

## WCAP-CSGP 1210, 885012209006
designator C?, comment 22μF pF
WCAP-CSGP MLCC, X7R, 1210, 22μF pF,10Vdc; Manufacturer: Wurth Elektronik; partNo: 885012209006; E-mail: libraries@we-online.com
footprint WCAP-CSGP 1210, H=2.5mm
pins: 1, 2

## WCAP-CSGP 1210, 885012209007
designator C?, comment 150000 pF
WCAP-CSGP MLCC, X7R, 1210, 150000 pF,16Vdc; Manufacturer: Wurth Elektronik; partNo: 885012209007; E-mail: libraries@we-online.com
footprint WCAP-CSGP 1210, H=0.95mm
pins: 1, 2

## WCAP-CSGP 1210, 885012209008
designator C?, comment 220000 pF
WCAP-CSGP MLCC, X7R, 1210, 220000 pF,16Vdc; Manufacturer: Wurth Elektronik; partNo: 885012209008; E-mail: libraries@we-online.com
footprint WCAP-CSGP 1210, H=0.95mm
pins: 1, 2

## WCAP-CSGP 1210, 885012209009
designator C?, comment 470000 pF
WCAP-CSGP MLCC, X7R, 1210, 470000 pF,16Vdc; Manufacturer: Wurth Elektronik; partNo: 885012209009; E-mail: libraries@we-online.com
footprint WCAP-CSGP 1210, H=0.95mm
pins: 1, 2

## WCAP-CSGP 1210, 885012209010
designator C?, comment 680000 pF
WCAP-CSGP MLCC, X7R, 1210, 680000 pF,16Vdc; Manufacturer: Wurth Elektronik; partNo: 885012209010; E-mail: libraries@we-online.com
footprint WCAP-CSGP 1210, H=1.25mm
pins: 1, 2

## WCAP-CSGP 1210, 885012209011
designator C?, comment 1μF pF
WCAP-CSGP MLCC, X7R, 1210, 1μF pF,16Vdc; Manufacturer: Wurth Elektronik; partNo: 885012209011; E-mail: libraries@we-online.com
footprint WCAP-CSGP 1210, H=1.25mm
pins: 1, 2

## WCAP-CSGP 1210, 885012209012
designator C?, comment 2.2μF pF
WCAP-CSGP MLCC, X7R, 1210, 2.2μF pF,16Vdc; Manufacturer: Wurth Elektronik; partNo: 885012209012; E-mail: libraries@we-online.com
footprint WCAP-CSGP 1210, H=2mm
pins: 1, 2

## WCAP-CSGP 1210, 885012209013
designator C?, comment 4.7μF pF
WCAP-CSGP MLCC, X7R, 1210, 4.7μF pF,16Vdc; Manufacturer: Wurth Elektronik; partNo: 885012209013; E-mail: libraries@we-online.com
footprint WCAP-CSGP 1210, H=2mm
pins: 1, 2

## WCAP-CSGP 1210, 885012209014
designator C?, comment 10μF pF
WCAP-CSGP MLCC, X7R, 1210, 10μF pF,16Vdc; Manufacturer: Wurth Elektronik; partNo: 885012209014; E-mail: libraries@we-online.com
footprint WCAP-CSGP 1210, H=2mm
pins: 1, 2

## WCAP-CSGP 1210, 885012209015
designator C?, comment 1000 pF
WCAP-CSGP MLCC, X7R, 1210, 1000 pF,25Vdc; Manufacturer: Wurth Elektronik; partNo: 885012209015; E-mail: libraries@we-online.com
footprint WCAP-CSGP 1210, H=0.95mm
pins: 1, 2

## WCAP-CSGP 1210, 885012209016
designator C?, comment 2200 pF
WCAP-CSGP MLCC, X7R, 1210, 2200 pF,25Vdc; Manufacturer: Wurth Elektronik; partNo: 885012209016; E-mail: libraries@we-online.com
footprint WCAP-CSGP 1210, H=0.95mm
pins: 1, 2

## WCAP-CSGP 1210, 885012209017
designator C?, comment 10000 pF
WCAP-CSGP MLCC, X7R, 1210, 10000 pF,25Vdc; Manufacturer: Wurth Elektronik; partNo: 885012209017; E-mail: libraries@we-online.com
footprint WCAP-CSGP 1210, H=0.95mm
pins: 1, 2

## WCAP-CSGP 1210, 885012209018
designator C?, comment 22000 pF
WCAP-CSGP MLCC, X7R, 1210, 22000 pF,25Vdc; Manufacturer: Wurth Elektronik; partNo: 885012209018; E-mail: libraries@we-online.com
footprint WCAP-CSGP 1210, H=0.95mm
pins: 1, 2

## WCAP-CSGP 1210, 885012209019
designator C?, comment 100000 pF
WCAP-CSGP MLCC, X7R, 1210, 100000 pF,25Vdc; Manufacturer: Wurth Elektronik; partNo: 885012209019; E-mail: libraries@we-online.com
footprint WCAP-CSGP 1210, H=0.95mm
pins: 1, 2

## WCAP-CSGP 1210, 885012209020
designator C?, comment 220000 pF
WCAP-CSGP MLCC, X7R, 1210, 220000 pF,25Vdc; Manufacturer: Wurth Elektronik; partNo: 885012209020; E-mail: libraries@we-online.com
footprint WCAP-CSGP 1210, H=0.95mm
pins: 1, 2

## WCAP-CSGP 1210, 885012209021
designator C?, comment 330000 pF
WCAP-CSGP MLCC, X7R, 1210, 330000 pF,25Vdc; Manufacturer: Wurth Elektronik; partNo: 885012209021; E-mail: libraries@we-online.com
footprint WCAP-CSGP 1210, H=0.95mm
pins: 1, 2

## WCAP-CSGP 1210, 885012209022
designator C?, comment 470000 pF
WCAP-CSGP MLCC, X7R, 1210, 470000 pF,25Vdc; Manufacturer: Wurth Elektronik; partNo: 885012209022; E-mail: libraries@we-online.com
footprint WCAP-CSGP 1210, H=0.95mm
pins: 1, 2

## WCAP-CSGP 1210, 885012209023
designator C?, comment 680000 pF
WCAP-CSGP MLCC, X7R, 1210, 680000 pF,25Vdc; Manufacturer: Wurth Elektronik; partNo: 885012209023; E-mail: libraries@we-online.com
footprint WCAP-CSGP 1210, H=1.25mm
pins: 1, 2

## WCAP-CSGP 1210, 885012209024
designator C?, comment 1μF pF
WCAP-CSGP MLCC, X7R, 1210, 1μF pF,25Vdc; Manufacturer: Wurth Elektronik; partNo: 885012209024; E-mail: libraries@we-online.com
footprint WCAP-CSGP 1210, H=1.25mm
pins: 1, 2

## WCAP-CSGP 1210, 885012209025
designator C?, comment 2.2μF pF
WCAP-CSGP MLCC, X7R, 1210, 2.2μF pF,25Vdc; Manufacturer: Wurth Elektronik; partNo: 885012209025; E-mail: libraries@we-online.com
footprint WCAP-CSGP 1210, H=1.6mm
pins: 1, 2

## WCAP-CSGP 1210, 885012209026
designator C?, comment 3.3μF pF
WCAP-CSGP MLCC, X7R, 1210, 3.3μF pF,25Vdc; Manufacturer: Wurth Elektronik; partNo: 885012209026; E-mail: libraries@we-online.com
footprint WCAP-CSGP 1210, H=1.6mm
pins: 1, 2

## WCAP-CSGP 1210, 885012209027
designator C?, comment 4.7μF pF
WCAP-CSGP MLCC, X7R, 1210, 4.7μF pF,25Vdc; Manufacturer: Wurth Elektronik; partNo: 885012209027; E-mail: libraries@we-online.com
footprint WCAP-CSGP 1210, H=2mm
pins: 1, 2

## WCAP-CSGP 1210, 885012209028
designator C?, comment 10μF pF
WCAP-CSGP MLCC, X7R, 1210, 10μF pF,25Vdc; Manufacturer: Wurth Elektronik; partNo: 885012209028; E-mail: libraries@we-online.com
footprint WCAP-CSGP 1210, H=2mm
pins: 1, 2

## WCAP-CSGP 1210, 885012209029
designator C?, comment 1000 pF
WCAP-CSGP MLCC, X7R, 1210, 1000 pF,50Vdc; Manufacturer: Wurth Elektronik; partNo: 885012209029; E-mail: libraries@we-online.com
footprint WCAP-CSGP 1210, H=0.95mm
pins: 1, 2

## WCAP-CSGP 1210, 885012209030
designator C?, comment 1500 pF
WCAP-CSGP MLCC, X7R, 1210, 1500 pF,50Vdc; Manufacturer: Wurth Elektronik; partNo: 885012209030; E-mail: libraries@we-online.com
footprint WCAP-CSGP 1210, H=0.95mm
pins: 1, 2

## WCAP-CSGP 1210, 885012209031
designator C?, comment 2200 pF
WCAP-CSGP MLCC, X7R, 1210, 2200 pF,50Vdc; Manufacturer: Wurth Elektronik; partNo: 885012209031; E-mail: libraries@we-online.com
footprint WCAP-CSGP 1210, H=0.95mm
pins: 1, 2

## WCAP-CSGP 1210, 885012209032
designator C?, comment 3300 pF
WCAP-CSGP MLCC, X7R, 1210, 3300 pF,50Vdc; Manufacturer: Wurth Elektronik; partNo: 885012209032; E-mail: libraries@we-online.com
footprint WCAP-CSGP 1210, H=0.95mm
pins: 1, 2

## WCAP-CSGP 1210, 885012209033
designator C?, comment 4700 pF
WCAP-CSGP MLCC, X7R, 1210, 4700 pF,50Vdc; Manufacturer: Wurth Elektronik; partNo: 885012209033; E-mail: libraries@we-online.com
footprint WCAP-CSGP 1210, H=0.95mm
pins: 1, 2

## WCAP-CSGP 1210, 885012209034
designator C?, comment 6800 pF
WCAP-CSGP MLCC, X7R, 1210, 6800 pF,50Vdc; Manufacturer: Wurth Elektronik; partNo: 885012209034; E-mail: libraries@we-online.com
footprint WCAP-CSGP 1210, H=0.95mm
pins: 1, 2

## WCAP-CSGP 1210, 885012209035
designator C?, comment 10000 pF
WCAP-CSGP MLCC, X7R, 1210, 10000 pF,50Vdc; Manufacturer: Wurth Elektronik; partNo: 885012209035; E-mail: libraries@we-online.com
footprint WCAP-CSGP 1210, H=0.95mm
pins: 1, 2

## WCAP-CSGP 1210, 885012209036
designator C?, comment 15000 pF
WCAP-CSGP MLCC, X7R, 1210, 15000 pF,50Vdc; Manufacturer: Wurth Elektronik; partNo: 885012209036; E-mail: libraries@we-online.com
footprint WCAP-CSGP 1210, H=0.95mm
pins: 1, 2

## WCAP-CSGP 1210, 885012209037
designator C?, comment 22000 pF
WCAP-CSGP MLCC, X7R, 1210, 22000 pF,50Vdc; Manufacturer: Wurth Elektronik; partNo: 885012209037; E-mail: libraries@we-online.com
footprint WCAP-CSGP 1210, H=0.95mm
pins: 1, 2

## WCAP-CSGP 1210, 885012209038
designator C?, comment 33000 pF
WCAP-CSGP MLCC, X7R, 1210, 33000 pF,50Vdc; Manufacturer: Wurth Elektronik; partNo: 885012209038; E-mail: libraries@we-online.com
footprint WCAP-CSGP 1210, H=0.95mm
pins: 1, 2

## WCAP-CSGP 1210, 885012209039
designator C?, comment 47000 pF
WCAP-CSGP MLCC, X7R, 1210, 47000 pF,50Vdc; Manufacturer: Wurth Elektronik; partNo: 885012209039; E-mail: libraries@we-online.com
footprint WCAP-CSGP 1210, H=0.95mm
pins: 1, 2

## WCAP-CSGP 1210, 885012209040
designator C?, comment 68000 pF
WCAP-CSGP MLCC, X7R, 1210, 68000 pF,50Vdc; Manufacturer: Wurth Elektronik; partNo: 885012209040; E-mail: libraries@we-online.com
footprint WCAP-CSGP 1210, H=0.95mm
pins: 1, 2

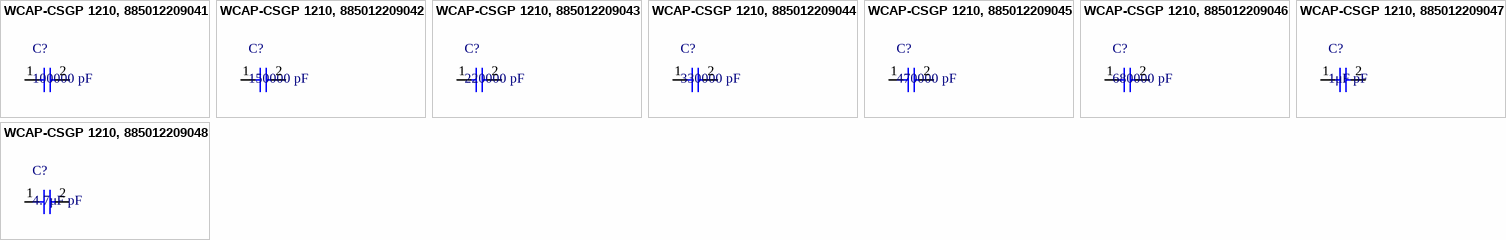
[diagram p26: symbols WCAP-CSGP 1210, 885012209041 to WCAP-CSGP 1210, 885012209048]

## WCAP-CSGP 1210, 885012209041
designator C?, comment 100000 pF
WCAP-CSGP MLCC, X7R, 1210, 100000 pF,50Vdc; Manufacturer: Wurth Elektronik; partNo: 885012209041; E-mail: libraries@we-online.com
footprint WCAP-CSGP 1210, H=0.95mm
pins: 1, 2

## WCAP-CSGP 1210, 885012209042
designator C?, comment 150000 pF
WCAP-CSGP MLCC, X7R, 1210, 150000 pF,50Vdc; Manufacturer: Wurth Elektronik; partNo: 885012209042; E-mail: libraries@we-online.com
footprint WCAP-CSGP 1210, H=0.95mm
pins: 1, 2

## WCAP-CSGP 1210, 885012209043
designator C?, comment 220000 pF
WCAP-CSGP MLCC, X7R, 1210, 220000 pF,50Vdc; Manufacturer: Wurth Elektronik; partNo: 885012209043; E-mail: libraries@we-online.com
footprint WCAP-CSGP 1210, H=0.95mm
pins: 1, 2

## WCAP-CSGP 1210, 885012209044
designator C?, comment 330000 pF
WCAP-CSGP MLCC, X7R, 1210, 330000 pF,50Vdc; Manufacturer: Wurth Elektronik; partNo: 885012209044; E-mail: libraries@we-online.com
footprint WCAP-CSGP 1210, H=1.25mm
pins: 1, 2

## WCAP-CSGP 1210, 885012209045
designator C?, comment 470000 pF
WCAP-CSGP MLCC, X7R, 1210, 470000 pF,50Vdc; Manufacturer: Wurth Elektronik; partNo: 885012209045; E-mail: libraries@we-online.com
footprint WCAP-CSGP 1210, H=1.25mm
pins: 1, 2

## WCAP-CSGP 1210, 885012209046
designator C?, comment 680000 pF
WCAP-CSGP MLCC, X7R, 1210, 680000 pF,50Vdc; Manufacturer: Wurth Elektronik; partNo: 885012209046; E-mail: libraries@we-online.com
footprint WCAP-CSGP 1210, H=1.25mm
pins: 1, 2

## WCAP-CSGP 1210, 885012209047
designator C?, comment 1μF pF
WCAP-CSGP MLCC, X7R, 1210, 1μF pF,50Vdc; Manufacturer: Wurth Elektronik; partNo: 885012209047; E-mail: libraries@we-online.com
footprint WCAP-CSGP 1210, H=1.25mm
pins: 1, 2

## WCAP-CSGP 1210, 885012209048
designator C?, comment 4.7μF pF
WCAP-CSGP MLCC, X7R, 1210, 4.7μF pF,50Vdc; Manufacturer: Wurth Elektronik; partNo: 885012209048; E-mail: libraries@we-online.com
footprint WCAP-CSGP 1210, H=2.5mm
pins: 1, 2


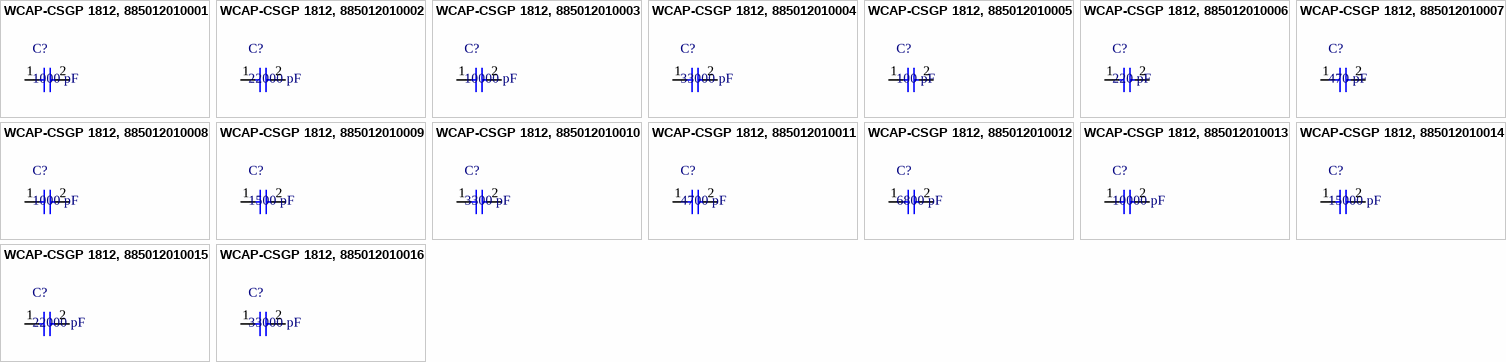
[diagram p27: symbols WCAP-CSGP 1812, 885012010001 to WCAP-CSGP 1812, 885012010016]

## WCAP-CSGP 1812, 885012010001
designator C?, comment 1000 pF
WCAP-CSGP MLCC, NP0, 1812, 1000 pF,16Vdc; Manufacturer: Wurth Elektronik; partNo: 885012010001; E-mail: libraries@we-online.com
footprint WCAP-CSGP 1812, H=1.25mm
pins: 1, 2

## WCAP-CSGP 1812, 885012010002
designator C?, comment 22000 pF
WCAP-CSGP MLCC, NP0, 1812, 22000 pF,16Vdc; Manufacturer: Wurth Elektronik; partNo: 885012010002; E-mail: libraries@we-online.com
footprint WCAP-CSGP 1812, H=1.25mm
pins: 1, 2

## WCAP-CSGP 1812, 885012010003
designator C?, comment 10000 pF
WCAP-CSGP MLCC, NP0, 1812, 10000 pF,25Vdc; Manufacturer: Wurth Elektronik; partNo: 885012010003; E-mail: libraries@we-online.com
footprint WCAP-CSGP 1812, H=1.25mm
pins: 1, 2

## WCAP-CSGP 1812, 885012010004
designator C?, comment 33000 pF
WCAP-CSGP MLCC, NP0, 1812, 33000 pF,25Vdc; Manufacturer: Wurth Elektronik; partNo: 885012010004; E-mail: libraries@we-online.com
footprint WCAP-CSGP 1812, H=1.25mm
pins: 1, 2

## WCAP-CSGP 1812, 885012010005
designator C?, comment 100 pF
WCAP-CSGP MLCC, NP0, 1812, 100 pF,50Vdc; Manufacturer: Wurth Elektronik; partNo: 885012010005; E-mail: libraries@we-online.com
footprint WCAP-CSGP 1812, H=1.25mm
pins: 1, 2

## WCAP-CSGP 1812, 885012010006
designator C?, comment 220 pF
WCAP-CSGP MLCC, NP0, 1812, 220 pF,50Vdc; Manufacturer: Wurth Elektronik; partNo: 885012010006; E-mail: libraries@we-online.com
footprint WCAP-CSGP 1812, H=1.25mm
pins: 1, 2

## WCAP-CSGP 1812, 885012010007
designator C?, comment 470 pF
WCAP-CSGP MLCC, NP0, 1812, 470 pF,50Vdc; Manufacturer: Wurth Elektronik; partNo: 885012010007; E-mail: libraries@we-online.com
footprint WCAP-CSGP 1812, H=1.25mm
pins: 1, 2

## WCAP-CSGP 1812, 885012010008
designator C?, comment 1000 pF
WCAP-CSGP MLCC, NP0, 1812, 1000 pF,50Vdc; Manufacturer: Wurth Elektronik; partNo: 885012010008; E-mail: libraries@we-online.com
footprint WCAP-CSGP 1812, H=1.25mm
pins: 1, 2

## WCAP-CSGP 1812, 885012010009
designator C?, comment 1500 pF
WCAP-CSGP MLCC, NP0, 1812, 1500 pF,50Vdc; Manufacturer: Wurth Elektronik; partNo: 885012010009; E-mail: libraries@we-online.com
footprint WCAP-CSGP 1812, H=1.25mm
pins: 1, 2

## WCAP-CSGP 1812, 885012010010
designator C?, comment 3300 pF
WCAP-CSGP MLCC, NP0, 1812, 3300 pF,50Vdc; Manufacturer: Wurth Elektronik; partNo: 885012010010; E-mail: libraries@we-online.com
footprint WCAP-CSGP 1812, H=1.25mm
pins: 1, 2

## WCAP-CSGP 1812, 885012010011
designator C?, comment 4700 pF
WCAP-CSGP MLCC, NP0, 1812, 4700 pF,50Vdc; Manufacturer: Wurth Elektronik; partNo: 885012010011; E-mail: libraries@we-online.com
footprint WCAP-CSGP 1812, H=1.25mm
pins: 1, 2

## WCAP-CSGP 1812, 885012010012
designator C?, comment 6800 pF
WCAP-CSGP MLCC, NP0, 1812, 6800 pF,50Vdc; Manufacturer: Wurth Elektronik; partNo: 885012010012; E-mail: libraries@we-online.com
footprint WCAP-CSGP 1812, H=1.25mm
pins: 1, 2

## WCAP-CSGP 1812, 885012010013
designator C?, comment 10000 pF
WCAP-CSGP MLCC, NP0, 1812, 10000 pF,50Vdc; Manufacturer: Wurth Elektronik; partNo: 885012010013; E-mail: libraries@we-online.com
footprint WCAP-CSGP 1812, H=1.25mm
pins: 1, 2

## WCAP-CSGP 1812, 885012010014
designator C?, comment 15000 pF
WCAP-CSGP MLCC, NP0, 1812, 15000 pF,50Vdc; Manufacturer: Wurth Elektronik; partNo: 885012010014; E-mail: libraries@we-online.com
footprint WCAP-CSGP 1812, H=1.25mm
pins: 1, 2

## WCAP-CSGP 1812, 885012010015
designator C?, comment 22000 pF
WCAP-CSGP MLCC, NP0, 1812, 22000 pF,50Vdc; Manufacturer: Wurth Elektronik; partNo: 885012010015; E-mail: libraries@we-online.com
footprint WCAP-CSGP 1812, H=1.25mm
pins: 1, 2

## WCAP-CSGP 1812, 885012010016
designator C?, comment 33000 pF
WCAP-CSGP MLCC, NP0, 1812, 33000 pF,50Vdc; Manufacturer: Wurth Elektronik; partNo: 885012010016; E-mail: libraries@we-online.com
footprint WCAP-CSGP 1812, H=1.25mm
pins: 1, 2


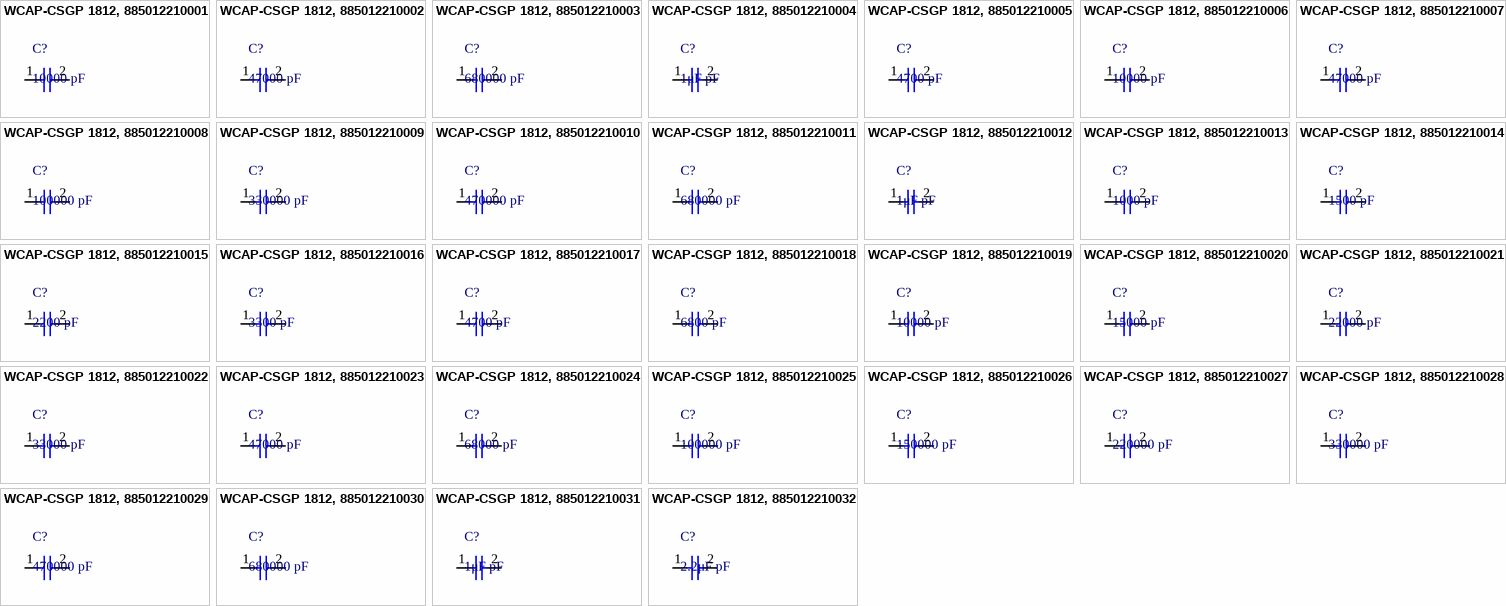
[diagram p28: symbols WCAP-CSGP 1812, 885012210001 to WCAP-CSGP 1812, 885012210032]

## WCAP-CSGP 1812, 885012210001
designator C?, comment 10000 pF
WCAP-CSGP MLCC, X7R, 1812, 10000 pF,16Vdc; Manufacturer: Wurth Elektronik; partNo: 885012210001; E-mail: libraries@we-online.com
footprint WCAP-CSGP 1812, H=1.25mm
pins: 1, 2

## WCAP-CSGP 1812, 885012210002
designator C?, comment 47000 pF
WCAP-CSGP MLCC, X7R, 1812, 47000 pF,16Vdc; Manufacturer: Wurth Elektronik; partNo: 885012210002; E-mail: libraries@we-online.com
footprint WCAP-CSGP 1812, H=1.25mm
pins: 1, 2

## WCAP-CSGP 1812, 885012210003
designator C?, comment 680000 pF
WCAP-CSGP MLCC, X7R, 1812, 680000 pF,16Vdc; Manufacturer: Wurth Elektronik; partNo: 885012210003; E-mail: libraries@we-online.com
footprint WCAP-CSGP 1812, H=1.25mm
pins: 1, 2

## WCAP-CSGP 1812, 885012210004
designator C?, comment 1μF pF
WCAP-CSGP MLCC, X7R, 1812, 1μF pF,16Vdc; Manufacturer: Wurth Elektronik; partNo: 885012210004; E-mail: libraries@we-online.com
footprint WCAP-CSGP 1812, H=1.25mm
pins: 1, 2

## WCAP-CSGP 1812, 885012210005
designator C?, comment 4700 pF
WCAP-CSGP MLCC, X7R, 1812, 4700 pF,25Vdc; Manufacturer: Wurth Elektronik; partNo: 885012210005; E-mail: libraries@we-online.com
footprint WCAP-CSGP 1812, H=1.25mm
pins: 1, 2

## WCAP-CSGP 1812, 885012210006
designator C?, comment 10000 pF
WCAP-CSGP MLCC, X7R, 1812, 10000 pF,25Vdc; Manufacturer: Wurth Elektronik; partNo: 885012210006; E-mail: libraries@we-online.com
footprint WCAP-CSGP 1812, H=1.25mm
pins: 1, 2

## WCAP-CSGP 1812, 885012210007
designator C?, comment 47000 pF
WCAP-CSGP MLCC, X7R, 1812, 47000 pF,25Vdc; Manufacturer: Wurth Elektronik; partNo: 885012210007; E-mail: libraries@we-online.com
footprint WCAP-CSGP 1812, H=1.25mm
pins: 1, 2

## WCAP-CSGP 1812, 885012210008
designator C?, comment 100000 pF
WCAP-CSGP MLCC, X7R, 1812, 100000 pF,25Vdc; Manufacturer: Wurth Elektronik; partNo: 885012210008; E-mail: libraries@we-online.com
footprint WCAP-CSGP 1812, H=1.25mm
pins: 1, 2

## WCAP-CSGP 1812, 885012210009
designator C?, comment 330000 pF
WCAP-CSGP MLCC, X7R, 1812, 330000 pF,25Vdc; Manufacturer: Wurth Elektronik; partNo: 885012210009; E-mail: libraries@we-online.com
footprint WCAP-CSGP 1812, H=1.25mm
pins: 1, 2

## WCAP-CSGP 1812, 885012210010
designator C?, comment 470000 pF
WCAP-CSGP MLCC, X7R, 1812, 470000 pF,25Vdc; Manufacturer: Wurth Elektronik; partNo: 885012210010; E-mail: libraries@we-online.com
footprint WCAP-CSGP 1812, H=1.25mm
pins: 1, 2

## WCAP-CSGP 1812, 885012210011
designator C?, comment 680000 pF
WCAP-CSGP MLCC, X7R, 1812, 680000 pF,25Vdc; Manufacturer: Wurth Elektronik; partNo: 885012210011; E-mail: libraries@we-online.com
footprint WCAP-CSGP 1812, H=1.25mm
pins: 1, 2

## WCAP-CSGP 1812, 885012210012
designator C?, comment 1μF pF
WCAP-CSGP MLCC, X7R, 1812, 1μF pF,25Vdc; Manufacturer: Wurth Elektronik; partNo: 885012210012; E-mail: libraries@we-online.com
footprint WCAP-CSGP 1812, H=1.25mm
pins: 1, 2

## WCAP-CSGP 1812, 885012210013
designator C?, comment 1000 pF
WCAP-CSGP MLCC, X7R, 1812, 1000 pF,50Vdc; Manufacturer: Wurth Elektronik; partNo: 885012210013; E-mail: libraries@we-online.com
footprint WCAP-CSGP 1812, H=1.25mm
pins: 1, 2

## WCAP-CSGP 1812, 885012210014
designator C?, comment 1500 pF
WCAP-CSGP MLCC, X7R, 1812, 1500 pF,50Vdc; Manufacturer: Wurth Elektronik; partNo: 885012210014; E-mail: libraries@we-online.com
footprint WCAP-CSGP 1812, H=1.25mm
pins: 1, 2

## WCAP-CSGP 1812, 885012210015
designator C?, comment 2200 pF
WCAP-CSGP MLCC, X7R, 1812, 2200 pF,50Vdc; Manufacturer: Wurth Elektronik; partNo: 885012210015; E-mail: libraries@we-online.com
footprint WCAP-CSGP 1812, H=1.25mm
pins: 1, 2

## WCAP-CSGP 1812, 885012210016
designator C?, comment 3300 pF
WCAP-CSGP MLCC, X7R, 1812, 3300 pF,50Vdc; Manufacturer: Wurth Elektronik; partNo: 885012210016; E-mail: libraries@we-online.com
footprint WCAP-CSGP 1812, H=1.25mm
pins: 1, 2

## WCAP-CSGP 1812, 885012210017
designator C?, comment 4700 pF
WCAP-CSGP MLCC, X7R, 1812, 4700 pF,50Vdc; Manufacturer: Wurth Elektronik; partNo: 885012210017; E-mail: libraries@we-online.com
footprint WCAP-CSGP 1812, H=1.25mm
pins: 1, 2

## WCAP-CSGP 1812, 885012210018
designator C?, comment 6800 pF
WCAP-CSGP MLCC, X7R, 1812, 6800 pF,50Vdc; Manufacturer: Wurth Elektronik; partNo: 885012210018; E-mail: libraries@we-online.com
footprint WCAP-CSGP 1812, H=1.25mm
pins: 1, 2

## WCAP-CSGP 1812, 885012210019
designator C?, comment 10000 pF
WCAP-CSGP MLCC, X7R, 1812, 10000 pF,50Vdc; Manufacturer: Wurth Elektronik; partNo: 885012210019; E-mail: libraries@we-online.com
footprint WCAP-CSGP 1812, H=1.25mm
pins: 1, 2

## WCAP-CSGP 1812, 885012210020
designator C?, comment 15000 pF
WCAP-CSGP MLCC, X7R, 1812, 15000 pF,50Vdc; Manufacturer: Wurth Elektronik; partNo: 885012210020; E-mail: libraries@we-online.com
footprint WCAP-CSGP 1812, H=1.25mm
pins: 1, 2

## WCAP-CSGP 1812, 885012210021
designator C?, comment 22000 pF
WCAP-CSGP MLCC, X7R, 1812, 22000 pF,50Vdc; Manufacturer: Wurth Elektronik; partNo: 885012210021; E-mail: libraries@we-online.com
footprint WCAP-CSGP 1812, H=1.25mm
pins: 1, 2

## WCAP-CSGP 1812, 885012210022
designator C?, comment 33000 pF
WCAP-CSGP MLCC, X7R, 1812, 33000 pF,50Vdc; Manufacturer: Wurth Elektronik; partNo: 885012210022; E-mail: libraries@we-online.com
footprint WCAP-CSGP 1812, H=1.25mm
pins: 1, 2

## WCAP-CSGP 1812, 885012210023
designator C?, comment 47000 pF
WCAP-CSGP MLCC, X7R, 1812, 47000 pF,50Vdc; Manufacturer: Wurth Elektronik; partNo: 885012210023; E-mail: libraries@we-online.com
footprint WCAP-CSGP 1812, H=1.25mm
pins: 1, 2

## WCAP-CSGP 1812, 885012210024
designator C?, comment 68000 pF
WCAP-CSGP MLCC, X7R, 1812, 68000 pF,50Vdc; Manufacturer: Wurth Elektronik; partNo: 885012210024; E-mail: libraries@we-online.com
footprint WCAP-CSGP 1812, H=1.25mm
pins: 1, 2

## WCAP-CSGP 1812, 885012210025
designator C?, comment 100000 pF
WCAP-CSGP MLCC, X7R, 1812, 100000 pF,50Vdc; Manufacturer: Wurth Elektronik; partNo: 885012210025; E-mail: libraries@we-online.com
footprint WCAP-CSGP 1812, H=1.25mm
pins: 1, 2

## WCAP-CSGP 1812, 885012210026
designator C?, comment 150000 pF
WCAP-CSGP MLCC, X7R, 1812, 150000 pF,50Vdc; Manufacturer: Wurth Elektronik; partNo: 885012210026; E-mail: libraries@we-online.com
footprint WCAP-CSGP 1812, H=1.25mm
pins: 1, 2

## WCAP-CSGP 1812, 885012210027
designator C?, comment 220000 pF
WCAP-CSGP MLCC, X7R, 1812, 220000 pF,50Vdc; Manufacturer: Wurth Elektronik; partNo: 885012210027; E-mail: libraries@we-online.com
footprint WCAP-CSGP 1812, H=1.25mm
pins: 1, 2

## WCAP-CSGP 1812, 885012210028
designator C?, comment 330000 pF
WCAP-CSGP MLCC, X7R, 1812, 330000 pF,50Vdc; Manufacturer: Wurth Elektronik; partNo: 885012210028; E-mail: libraries@we-online.com
footprint WCAP-CSGP 1812, H=1.25mm
pins: 1, 2

## WCAP-CSGP 1812, 885012210029
designator C?, comment 470000 pF
WCAP-CSGP MLCC, X7R, 1812, 470000 pF,50Vdc; Manufacturer: Wurth Elektronik; partNo: 885012210029; E-mail: libraries@we-online.com
footprint WCAP-CSGP 1812, H=1.25mm
pins: 1, 2

## WCAP-CSGP 1812, 885012210030
designator C?, comment 680000 pF
WCAP-CSGP MLCC, X7R, 1812, 680000 pF,50Vdc; Manufacturer: Wurth Elektronik; partNo: 885012210030; E-mail: libraries@we-online.com
footprint WCAP-CSGP 1812, H=2mm
pins: 1, 2

## WCAP-CSGP 1812, 885012210031
designator C?, comment 1μF pF
WCAP-CSGP MLCC, X7R, 1812, 1μF pF,50Vdc; Manufacturer: Wurth Elektronik; partNo: 885012210031; E-mail: libraries@we-online.com
footprint WCAP-CSGP 1812, H=2mm
pins: 1, 2

## WCAP-CSGP 1812, 885012210032
designator C?, comment 2.2μF pF
WCAP-CSGP MLCC, X7R, 1812, 2.2μF pF,50Vdc; Manufacturer: Wurth Elektronik; partNo: 885012210032; E-mail: libraries@we-online.com
footprint WCAP-CSGP 1812, H=2.5mm
pins: 1, 2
